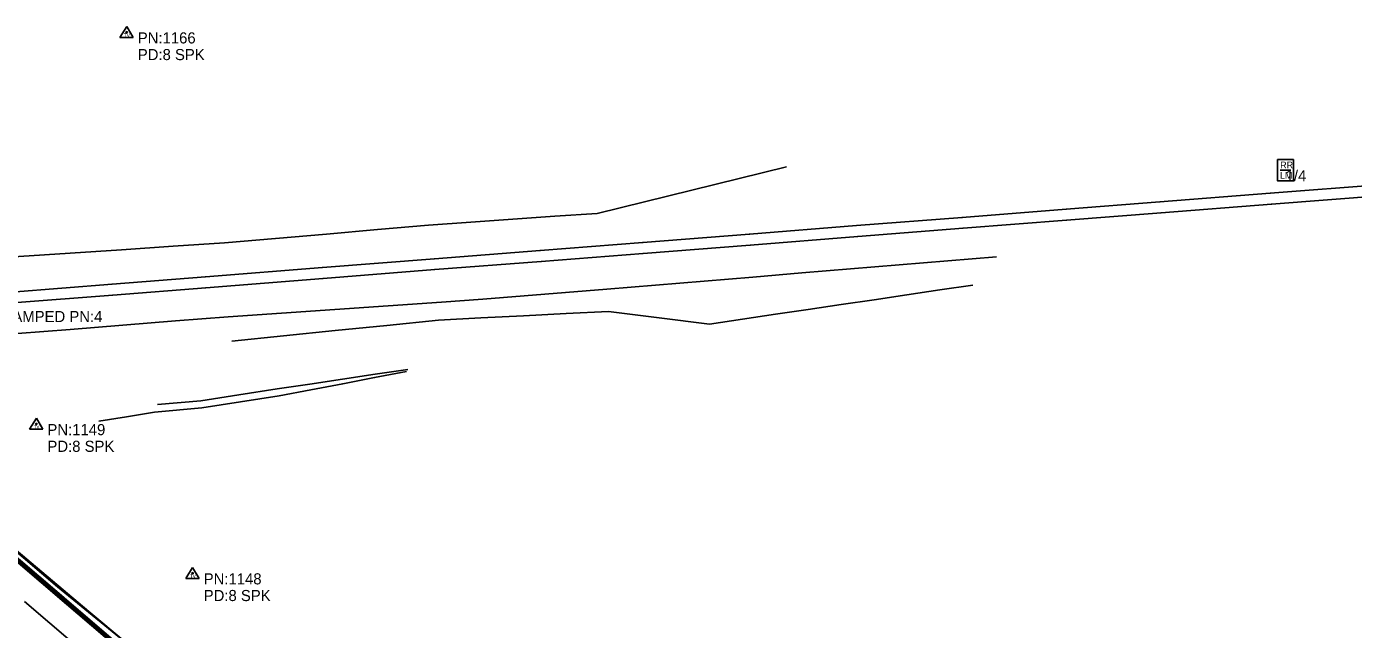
# Model space of a CAD drawing. Extents: x 878399 to 889864, y 1564003 to 1567413.
# Drawn here: x 884918 to 885515, y 1565340 to 1565611 of the extents above; entities that cross this region are included whole.
import ezdxf

# ---------------------------------------------------------------- set-up
doc = ezdxf.new("R2010")
doc.units = 0
for name, color, linetype in [('S_DITCHLINE', 7, 'Continuous'), ('S_EDGE_CONCRETE', 7, 'Continuous'), ('S_EDGE_PAVEMENT', 7, 'Continuous'), ('S_MSC_PT_SYM', 7, 'Continuous'), ('S_PAVEMENT_CROWN', 7, 'Continuous'), ('S_PRIMARY_CTL_ANNOT', 7, 'Continuous'), ('S_RAILROAD', 7, 'Continuous'), ('S_RAILROAD_ANNOT', 7, 'Continuous'), ('S_SECONDARY_CTL', 7, 'Continuous'), ('S_SECONDARY_CTL_ANNOT', 7, 'Continuous'), ('S_SHOULDER', 7, 'Continuous')]:
    doc.layers.add(name, color=color, linetype=linetype)

msp = doc.modelspace()

# ---------------------------------------------------------------- linework, layer by layer
at = {"layer": 'S_DITCHLINE'}
for points in [[(885259.5, 1565548.04), (885238.18, 1565542.79), (885216.85, 1565537.54), (885195.53, 1565532.29), (885174.2, 1565527.04)], [(885174.2, 1565527.04), (885155.25, 1565525.71), (885136.3, 1565524.37), (885117.35, 1565523.04), (885098.4, 1565521.7), (885075.43, 1565519.72), (885052.47, 1565517.74), (885029.5, 1565515.76), (885006.54, 1565513.77), (884983.43, 1565512.24), (884960.32, 1565510.7), (884937.21, 1565509.17), (884914.1, 1565507.63), (884893.55, 1565505.67), (884873, 1565503.7), (884852.45, 1565501.74), (884831.9, 1565499.77), (884819.17, 1565496.81), (884806.44, 1565493.86)], [(885353.98, 1565507.51), (885332.05, 1565505.69), (885310.12, 1565503.87), (885288.2, 1565502.05), (885266.27, 1565500.23), (885244.34, 1565498.41), (885222.41, 1565496.59), (885200.48, 1565494.77), (885178.55, 1565492.95)], [(885343.22, 1565494.79), (885328.42, 1565492.59), (885313.63, 1565490.4), (885298.83, 1565488.2), (885284.04, 1565486.01), (885269.24, 1565483.82), (885254.44, 1565481.62), (885239.65, 1565479.43), (885224.85, 1565477.23)], [(885178.55, 1565492.95), (885159.98, 1565491.47), (885141.41, 1565489.99), (885122.84, 1565488.51), (885104.27, 1565487.03), (885080.26, 1565485.4), (885056.25, 1565483.78), (885032.25, 1565482.15), (885008.24, 1565480.52), (884984.53, 1565478.63), (884960.82, 1565476.75), (884937.11, 1565474.86), (884913.41, 1565472.97), (884896.88, 1565471.54), (884880.36, 1565470.1), (884863.84, 1565468.66), (884847.32, 1565467.23)], [(885179.41, 1565482.89), (885160.26, 1565481.92), (885141.11, 1565480.96), (885121.96, 1565479.99), (885102.81, 1565479.03), (885079.56, 1565476.66), (885056.32, 1565474.29), (885033.07, 1565471.93), (885009.82, 1565469.56)], [(885224.85, 1565477.23), (885202.13, 1565480.06), (885179.41, 1565482.89)], [(885088.44, 1565455.9), (885074.13, 1565453.15), (885059.81, 1565450.41), (885045.5, 1565447.66), (885031.18, 1565444.92), (885013.8, 1565442.21), (884996.42, 1565439.5), (884975.14, 1565437.62), (884962.56, 1565435.57), (884949.98, 1565433.53)], [(885089.05, 1565456.85), (885074.37, 1565454.65), (885059.68, 1565452.45), (885045, 1565450.26), (885030.31, 1565448.06), (885013.09, 1565445.41), (884995.87, 1565442.76), (884976.48, 1565441.03)], [(884961.88, 1565334.22), (884945.54, 1565347.97), (884929.2, 1565361.71), (884912.86, 1565375.45)]]:
    msp.add_lwpolyline(points, dxfattribs=at)
at = {"layer": 'S_EDGE_CONCRETE'}
for points in [[(884705.4, 1565550.04), (884723.26, 1565534.58), (884742.1, 1565518.69), (884780.16, 1565486.23), (884818.14, 1565453.73), (884855.98, 1565421.17), (884892.08, 1565390.2), (884930.32, 1565357.68), (884968.08, 1565325.3), (885005.99, 1565292.69), (885044.06, 1565260.33), (885082.07, 1565227.99), (885120, 1565195.47), (885157.99, 1565163.2), (885196.4, 1565131.24), (885234.81, 1565099.94), (885295.36, 1565052.86), (885310.26, 1565042.23)], [(884706.6, 1565551.45), (884725.44, 1565537.13), (884744.17, 1565521.12), (884782.46, 1565488.91), (884820.33, 1565456.29), (884857.4, 1565422.83), (884893.19, 1565391.5), (884931.44, 1565358.94), (884969.96, 1565327.51), (885007.93, 1565294.95), (885045.65, 1565262.19), (885083.76, 1565229.98), (885121.86, 1565197.67), (885159.74, 1565165.3), (885198.19, 1565133.4), (885236.59, 1565102.25), (885296.12, 1565053.84), (885311.12, 1565043.35)]]:
    msp.add_lwpolyline(points, dxfattribs=at)
at = {"layer": 'S_EDGE_PAVEMENT'}
for points in [[(884912.75, 1565370.69), (884924.15, 1565360.95), (884935.54, 1565351.21), (884946.77, 1565341.58), (884958.15, 1565331.82)], [(884913.16, 1565370.98), (884924.56, 1565361.24), (884935.95, 1565351.49), (884947.18, 1565341.87), (884958.56, 1565332.11)]]:
    msp.add_lwpolyline(points, dxfattribs=at)
at = {"layer": 'S_MSC_PT_SYM'}
for points in [[(885427.48, 1565532.2), (885427.48, 1565532.25), (885427.48, 1565532.2), (885427.43, 1565532.2), (885427.48, 1565532.2), (885427.48, 1565532.15), (885427.48, 1565532.2), (885427.53, 1565532.2)], [(885477.1, 1565536.1), (885477.1, 1565536.15), (885477.1, 1565536.1), (885477.05, 1565536.1), (885477.1, 1565536.1), (885477.1, 1565536.05), (885477.1, 1565536.1), (885477.15, 1565536.1)], [(885477.65, 1565531.19), (885477.65, 1565531.24), (885477.65, 1565531.19), (885477.6, 1565531.19), (885477.65, 1565531.19), (885477.65, 1565531.14), (885477.65, 1565531.19), (885477.7, 1565531.19)], [(885338.52, 1565525.23), (885338.52, 1565525.28), (885338.52, 1565525.23), (885338.47, 1565525.23), (885338.52, 1565525.23), (885338.52, 1565525.18), (885338.52, 1565525.23), (885338.57, 1565525.23)], [(885385.28, 1565528.9), (885385.28, 1565528.95), (885385.28, 1565528.9), (885385.23, 1565528.9), (885385.28, 1565528.9), (885385.28, 1565528.85), (885385.28, 1565528.9), (885385.33, 1565528.9)], [(885427.99, 1565527.3), (885427.99, 1565527.35), (885427.99, 1565527.3), (885427.94, 1565527.3), (885427.99, 1565527.3), (885427.99, 1565527.25), (885427.99, 1565527.3), (885428.04, 1565527.3)], [(885290.92, 1565521.51), (885290.92, 1565521.56), (885290.92, 1565521.51), (885290.87, 1565521.51), (885290.92, 1565521.51), (885290.92, 1565521.46), (885290.92, 1565521.51), (885290.97, 1565521.51)], [(885338.87, 1565520.34), (885338.87, 1565520.39), (885338.87, 1565520.34), (885338.82, 1565520.34), (885338.87, 1565520.34), (885338.87, 1565520.29), (885338.87, 1565520.34), (885338.92, 1565520.34)], [(885385.47, 1565523.93), (885385.47, 1565523.98), (885385.47, 1565523.93), (885385.42, 1565523.93), (885385.47, 1565523.93), (885385.47, 1565523.88), (885385.47, 1565523.93), (885385.52, 1565523.93)], [(885194.83, 1565513.98), (885194.83, 1565514.03), (885194.83, 1565513.98), (885194.78, 1565513.98), (885194.83, 1565513.98), (885194.83, 1565513.93), (885194.83, 1565513.98), (885194.88, 1565513.98)], [(885242.8, 1565517.73), (885242.8, 1565517.78), (885242.8, 1565517.73), (885242.75, 1565517.73), (885242.8, 1565517.73), (885242.8, 1565517.68), (885242.8, 1565517.73), (885242.85, 1565517.73)], [(885243.16, 1565512.79), (885243.16, 1565512.84), (885243.16, 1565512.79), (885243.11, 1565512.79), (885243.16, 1565512.79), (885243.16, 1565512.74), (885243.16, 1565512.79), (885243.21, 1565512.79)], [(885291.46, 1565516.58), (885291.46, 1565516.63), (885291.46, 1565516.58), (885291.41, 1565516.58), (885291.46, 1565516.58), (885291.46, 1565516.53), (885291.46, 1565516.58), (885291.52, 1565516.58)], [(885101.01, 1565506.62), (885101.01, 1565506.67), (885101.01, 1565506.62), (885100.96, 1565506.62), (885101.01, 1565506.62), (885101.01, 1565506.57), (885101.01, 1565506.62), (885101.06, 1565506.62)], [(885148.64, 1565510.35), (885148.64, 1565510.4), (885148.64, 1565510.35), (885148.59, 1565510.35), (885148.64, 1565510.35), (885148.64, 1565510.3), (885148.64, 1565510.35), (885148.69, 1565510.35)], [(885194.95, 1565509), (885194.95, 1565509.05), (885194.95, 1565509), (885194.9, 1565509), (885194.95, 1565509), (885194.95, 1565508.95), (885194.95, 1565509), (885195, 1565509)], [(885050.65, 1565502.64), (885050.65, 1565502.69), (885050.65, 1565502.64), (885050.6, 1565502.64), (885050.65, 1565502.64), (885050.65, 1565502.59), (885050.65, 1565502.64), (885050.7, 1565502.64)], [(885101.21, 1565501.76), (885101.21, 1565501.81), (885101.21, 1565501.76), (885101.16, 1565501.76), (885101.21, 1565501.76), (885101.21, 1565501.71), (885101.21, 1565501.76), (885101.26, 1565501.76)], [(885149.12, 1565505.43), (885149.12, 1565505.48), (885149.12, 1565505.43), (885149.07, 1565505.43), (885149.12, 1565505.43), (885149.12, 1565505.38), (885149.12, 1565505.43), (885149.17, 1565505.43)], [(884956.06, 1565495.25), (884956.06, 1565495.3), (884956.06, 1565495.25), (884956.01, 1565495.25), (884956.06, 1565495.25), (884956.06, 1565495.2), (884956.06, 1565495.25), (884956.11, 1565495.25)], [(884997.99, 1565498.53), (884997.99, 1565498.58), (884997.99, 1565498.53), (884997.94, 1565498.53), (884997.99, 1565498.53), (884997.99, 1565498.48), (884997.99, 1565498.53), (884998.04, 1565498.53)], [(885050.97, 1565497.69), (885050.97, 1565497.74), (885050.97, 1565497.69), (885050.92, 1565497.69), (885050.97, 1565497.69), (885050.97, 1565497.64), (885050.97, 1565497.69), (885051.02, 1565497.69)], [(884956.36, 1565490.3), (884956.36, 1565490.35), (884956.36, 1565490.3), (884956.31, 1565490.3), (884956.36, 1565490.3), (884956.36, 1565490.25), (884956.36, 1565490.3), (884956.41, 1565490.3)], [(884998.21, 1565493.59), (884998.21, 1565493.64), (884998.21, 1565493.59), (884998.16, 1565493.59), (884998.21, 1565493.59), (884998.21, 1565493.54), (884998.21, 1565493.59), (884998.26, 1565493.59)]]:
    msp.add_lwpolyline(points, dxfattribs=at)
at = {"layer": 'S_PAVEMENT_CROWN'}
msp.add_lwpolyline([(884916.6, 1565352.44), (884928, 1565342.7), (884939.41, 1565332.94)], dxfattribs=at)
at = {"layer": 'S_RAILROAD'}
for p, q in [((885484.01, 1565551.25), (885487.61, 1565551.25)), ((885481.61, 1565546.45), (885486.41, 1565546.45)), ((885527.93, 1565540.08), (885477.1, 1565536.1)), ((885484.01, 1565541.65), (885480.41, 1565541.65)), ((885427.48, 1565532.2), (885385.28, 1565528.9)), ((885477.1, 1565536.1), (885427.48, 1565532.2)), ((885477.65, 1565531.19), (885427.99, 1565527.3)), ((885528.29, 1565535.15), (885477.65, 1565531.19)), ((885338.52, 1565525.23), (885290.92, 1565521.51)), ((885385.28, 1565528.9), (885338.52, 1565525.23)), ((885427.99, 1565527.3), (885385.47, 1565523.93)), ((885290.92, 1565521.51), (885242.8, 1565517.73)), ((885338.87, 1565520.34), (885291.46, 1565516.58)), ((885385.47, 1565523.93), (885338.87, 1565520.34)), ((885194.83, 1565513.98), (885148.64, 1565510.35)), ((885242.8, 1565517.73), (885194.83, 1565513.98)), ((885243.16, 1565512.79), (885194.95, 1565509)), ((885291.46, 1565516.58), (885243.16, 1565512.79)), ((885101.01, 1565506.62), (885050.65, 1565502.64)), ((885148.64, 1565510.35), (885101.01, 1565506.62)), ((885194.95, 1565509), (885149.12, 1565505.43)), ((885050.65, 1565502.64), (884997.99, 1565498.53)), ((885101.21, 1565501.76), (885050.97, 1565497.69)), ((885149.12, 1565505.43), (885101.21, 1565501.76)), ((884956.06, 1565495.25), (884910.78, 1565491.61)), ((884997.99, 1565498.53), (884956.06, 1565495.25)), ((885050.97, 1565497.69), (884998.21, 1565493.59)), ((884956.36, 1565490.3), (884911.4, 1565486.76)), ((884998.21, 1565493.59), (884956.36, 1565490.3))]:
    msp.add_line(p, q, dxfattribs=at)
msp.add_lwpolyline([(885487.61, 1565551.25), (885480.41, 1565551.25), (885480.41, 1565541.65), (885487.61, 1565541.65)], close=True, dxfattribs=at)
at = {"layer": 'S_SECONDARY_CTL'}
for p, q in [((884962.58, 1565611.1), (884959.57, 1565606.14)), ((884962.58, 1565611.1), (884965.52, 1565606.14)), ((884959.57, 1565606.14), (884965.52, 1565606.14)), ((884921.93, 1565434.85), (884918.92, 1565429.9)), ((884921.93, 1565434.85), (884924.87, 1565429.9)), ((884918.92, 1565429.9), (884924.87, 1565429.9)), ((884992.24, 1565367.71), (884989.23, 1565362.76)), ((884992.24, 1565367.71), (884995.19, 1565362.76)), ((884989.23, 1565362.76), (884995.19, 1565362.76))]:
    msp.add_line(p, q, dxfattribs=at)
for centre, radius in [((884962.58, 1565608.49), 0.311), ((884962.58, 1565608.49), 0.183), ((884962.58, 1565608.49), 0.103), ((884921.93, 1565432.24), 0.311), ((884921.93, 1565432.24), 0.183), ((884921.93, 1565432.24), 0.103), ((884992.24, 1565365.1), 0.311), ((884992.24, 1565365.1), 0.183), ((884992.24, 1565365.1), 0.103)]:
    msp.add_circle(centre, radius, dxfattribs=at)
at = {"layer": 'S_SHOULDER'}
msp.add_lwpolyline([(884891.75, 1565389.81), (884929.91, 1565357.22), (884967.7, 1565324.86), (885005.68, 1565292.33), (885043.8, 1565260.03), (885081.58, 1565227.41), (885119.6, 1565195.01), (885157.6, 1565162.73), (885196.01, 1565130.77), (885234.52, 1565099.56), (885295.12, 1565052.54), (885309.99, 1565041.88), (885349.92, 1565012.53), (885393.73, 1564987.91), (885434.98, 1564961), (885477.34, 1564934.42), (885519.82, 1564908.04)], dxfattribs=at)

# ---------------------------------------------------------------- texts
at = {"layer": 'S_PRIMARY_CTL_ANNOT'}
msp.add_text('PD:ARDOT STD. MON. STAMPED PN:4', height=5, dxfattribs=at).set_placement((884829.81, 1565478.13))
at = {"layer": 'S_RAILROAD'}
for s, p in [('RR', (885481.57, 1565547.3)), ('LM', (885481.47, 1565542.61))]:
    msp.add_text(s, height=3, rotation=360, dxfattribs=at).set_placement(p)
at = {"layer": 'S_RAILROAD_ANNOT'}
msp.add_text('1/4', height=5, dxfattribs=at).set_placement((885484.01, 1565541.45))
at = {"layer": 'S_SECONDARY_CTL'}
for p in [(884961.37, 1565606.48), (884920.72, 1565430.23), (884991.04, 1565363.09)]:
    msp.add_text('TV', height=1.5, rotation=360, dxfattribs=at).set_placement(p)
at = {"layer": 'S_SECONDARY_CTL_ANNOT'}
for s, p in [('PN:1166', (884967.58, 1565603.49)), ('PD:8 SPK', (884967.58, 1565595.99)), ('PN:1149', (884926.93, 1565427.24)), ('PD:8 SPK', (884926.93, 1565419.74)), ('PN:1148', (884997.24, 1565360.1)), ('PD:8 SPK', (884997.24, 1565352.6))]:
    msp.add_text(s, height=5, dxfattribs=at).set_placement(p)

doc.saveas('drawing.dxf')
